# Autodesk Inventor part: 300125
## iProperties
Created: 2007-12
Part Number: 300125
Document SubType Name: Modeling
Designer: MM
Density: 7.85 g/cm^3
Mass: 603.846 g
Surface Area: 1574.23 cm^2
Volume: 76.9231 cm^3
Material: Steel
Description: LEFT SIDE BACK MEMBER
Component Category: Back Component
Author: MM
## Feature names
1. TaggingFeature2
